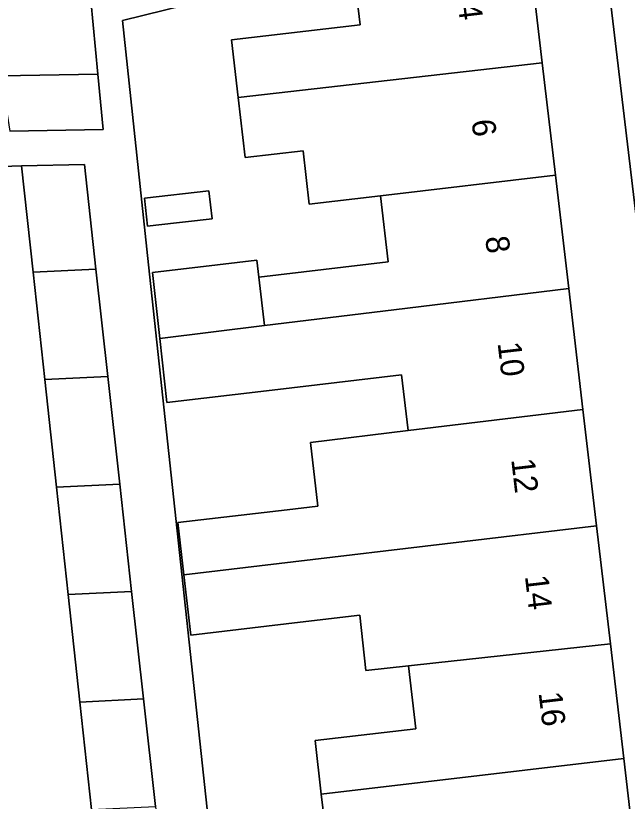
# Model space of a CAD drawing. Extents: x 162250 to 162661, y 380743 to 381606.
# Drawn here: x 162420.44 to 162446.47, y 381068.12 to 381101.54 of the extents above; entities that cross this region are included whole.
import ezdxf

# ---------------------------------------------------------------- set-up
doc = ezdxf.new("R2010")
doc.units = 0
for name, color, linetype in [('IMGEO_Erf', 7, 'Continuous'), ('IMGEO_Pand', 7, 'Continuous'), ('IMGEO_Pand_nummerreeks', 7, 'Continuous'), ('IMGEO_Voetpad_open', 7, 'Continuous')]:
    doc.layers.add(name, color=color, linetype=linetype)

msp = doc.modelspace()

# ---------------------------------------------------------------- linework, layer by layer
at = {"layer": 'IMGEO_Erf'}
for points in [[(162401.417, 381114.323), (162402.29, 381096.222), (162405.41, 381096.372), (162405.189, 381098.733), (162410.189, 381098.82), (162410.314, 381098.822), (162415.147, 381098.907), (162419.818, 381098.989), (162423.934, 381099.061), (162423.638, 381102.209)], [(162457.834, 381000), (162450.879, 381059.205), (162445.423, 381105.014)], [(162442.256, 381104.637), (162442.854, 381099.538), (162443.415, 381094.753), (162443.98, 381089.943), (162444.584, 381084.793), (162445.165, 381079.841), (162445.754, 381074.817), (162446.326, 381069.944), (162446.912, 381064.945), (162447.489, 381060.029), (162448.075, 381055.028), (162448.666, 381049.988), (162449.259, 381044.932), (162449.836, 381040.015), (162450.423, 381035.011)], [(162433.763, 381065.742), (162433.448, 381068.428), (162433.18, 381070.706), (162437.476, 381071.21), (162437.162, 381073.882), (162435.35, 381073.685), (162435.094, 381076.041), (162432.55, 381075.742), (162427.895, 381075.195), (162427.594, 381077.76), (162427.333, 381079.982), (162431.988, 381080.528), (162433.301, 381080.682), (162432.984, 381083.392), (162437.146, 381083.895), (162436.868, 381086.264), (162431.356, 381085.617), (162426.865, 381085.09), (162426.568, 381087.813), (162426.262, 381090.621), (162429.032, 381090.946), (162430.707, 381091.143), (162430.792, 381090.42), (162436.293, 381091.066), (162435.962, 381093.885), (162432.937, 381093.528), (162432.67, 381095.8), (162430.213, 381095.511), (162429.914, 381098.061), (162429.626, 381100.509), (162435.098, 381101.151), (162434.792, 381103.761), (162424.979, 381101.344), (162426.098, 381090.941), (162429.65, 381057.925)], [(162427.162, 381035.768), (162426.663, 381040.34), (162426.164, 381044.913), (162425.666, 381049.485), (162425.167, 381054.057), (162424.668, 381058.631), (162424.169, 381063.202), (162423.671, 381067.775), (162423.172, 381072.346), (162422.673, 381076.919), (162422.175, 381081.49), (162421.676, 381086.063), (162421.177, 381090.633), (162420.683, 381095.161), (162412.421, 381094.865)]]:
    msp.add_lwpolyline(points, dxfattribs=at)
msp.add_lwpolyline([(162426.048, 381092.583), (162425.918, 381093.776), (162428.662, 381094.098), (162428.802, 381092.906), (162426.402, 381092.625)], close=True, dxfattribs=at)
at = {"layer": 'IMGEO_Pand'}
for points in [[(162429.914, 381098.061), (162442.854, 381099.538), (162442.256, 381104.637), (162437.291, 381104.054), (162434.792, 381103.761), (162435.098, 381101.151), (162429.626, 381100.509)], [(162442.854, 381099.538), (162429.914, 381098.061), (162430.213, 381095.511), (162432.67, 381095.8), (162432.937, 381093.528), (162435.962, 381093.885), (162443.415, 381094.753)], [(162420.193, 381096.631), (162424.156, 381096.7), (162423.934, 381099.061), (162419.818, 381098.989)], [(162421.177, 381090.633), (162423.856, 381090.762), (162423.364, 381095.214), (162420.683, 381095.161)], [(162443.415, 381094.753), (162435.962, 381093.885), (162436.293, 381091.066), (162430.792, 381090.42), (162431.034, 381088.359), (162436.533, 381089.032), (162443.98, 381089.943)], [(162428.662, 381094.098), (162425.918, 381093.776), (162426.048, 381092.583), (162426.402, 381092.625), (162428.802, 381092.906)], [(162430.792, 381090.42), (162430.707, 381091.143), (162429.032, 381090.946), (162426.262, 381090.621), (162426.568, 381087.813), (162431.034, 381088.359)], [(162421.676, 381086.063), (162424.362, 381086.193), (162423.856, 381090.762), (162421.177, 381090.633)], [(162443.98, 381089.943), (162436.533, 381089.032), (162431.034, 381088.359), (162426.568, 381087.813), (162426.865, 381085.09), (162431.356, 381085.617), (162436.868, 381086.264), (162437.146, 381083.895), (162444.584, 381084.793)], [(162421.676, 381086.063), (162422.175, 381081.49), (162424.868, 381081.619), (162424.362, 381086.193)], [(162444.584, 381084.793), (162437.146, 381083.895), (162432.984, 381083.392), (162433.301, 381080.682), (162431.988, 381080.528), (162427.333, 381079.982), (162427.594, 381077.76), (162432.248, 381078.311), (162445.165, 381079.841)], [(162422.175, 381081.49), (162422.673, 381076.919), (162425.373, 381077.048), (162424.868, 381081.619)], [(162445.165, 381079.841), (162432.248, 381078.311), (162427.594, 381077.76), (162427.895, 381075.195), (162432.55, 381075.742), (162435.094, 381076.041), (162435.35, 381073.685), (162437.162, 381073.882), (162438.325, 381074.009), (162445.754, 381074.817)], [(162425.879, 381072.476), (162425.373, 381077.048), (162422.673, 381076.919), (162423.172, 381072.346)], [(162445.754, 381074.817), (162438.325, 381074.009), (162437.162, 381073.882), (162437.476, 381071.21), (162433.18, 381070.706), (162433.448, 381068.428), (162446.326, 381069.944)], [(162423.671, 381067.775), (162426.385, 381067.905), (162425.879, 381072.476), (162423.172, 381072.346)], [(162439.467, 381064.106), (162446.912, 381064.945), (162446.326, 381069.944), (162433.448, 381068.428), (162433.763, 381065.742), (162439.2, 381066.38)]]:
    msp.add_lwpolyline(points, close=True, dxfattribs=at)
at = {"layer": 'IMGEO_Voetpad_open'}
for points in [[(162448.012, 381094.82), (162447.671, 381097.419), (162445.147, 381119.325), (162444.787, 381121.617), (162446.621, 381121.794), (162446.181, 381124.863), (162443.007, 381124.274), (162443.348, 381122.437), (162445.298, 381106.063), (162445.423, 381105.014), (162450.879, 381059.205), (162457.834, 381000), (162460.106, 380980.583), (162460.3, 380978.923), (162460.973, 380973.177), (162462.017, 380963.112), (162463.931, 380963.326), (162465.132, 380963.42), (162465.07, 380964.466), (162464.578, 380964.604), (162463.577, 380964.503)], [(162432.376, 381032.96), (162431.951, 381036.788), (162431.777, 381038.35), (162431.293, 381042.709), (162431.089, 381044.542), (162430.974, 381044.529), (162430.172, 381051.464), (162430.361, 381051.486), (162430.022, 381054.466), (162429.771, 381056.807), (162429.752, 381056.977), (162429.725, 381057.231), (162429.68, 381057.648), (162429.65, 381057.925), (162426.098, 381090.941), (162424.979, 381101.344), (162434.792, 381103.761)], [(162423.638, 381102.209), (162423.934, 381099.061), (162424.156, 381096.7), (162420.193, 381096.631)], [(162412.421, 381094.865), (162420.683, 381095.161), (162423.364, 381095.214), (162423.856, 381090.762), (162424.362, 381086.193), (162424.868, 381081.619), (162425.373, 381077.048), (162425.879, 381072.476), (162426.385, 381067.905), (162426.89, 381063.333), (162427.396, 381058.762), (162427.902, 381054.188), (162428.408, 381049.616), (162428.913, 381045.045), (162429.419, 381040.472), (162429.925, 381035.901)]]:
    msp.add_lwpolyline(points, dxfattribs=at)

# ---------------------------------------------------------------- texts
at = {"layer": 'IMGEO_Pand_nummerreeks'}
for s, rotation, p in [('4', 276.6903, (162439.257, 381102.048)), ('6', 276.6919, (162439.84, 381097.087)), ('8', 276.6919, (162440.423, 381092.122)), ('10', 276.6919, (162440.949, 381087.619)), ('12', 276.6919, (162441.53, 381082.664)), ('14', 276.6919, (162442.113, 381077.7)), ('16', 276.6903, (162442.695, 381072.741))]:
    msp.add_text(s, height=1, rotation=rotation, dxfattribs=at).set_placement(p)

doc.saveas('drawing.dxf')
